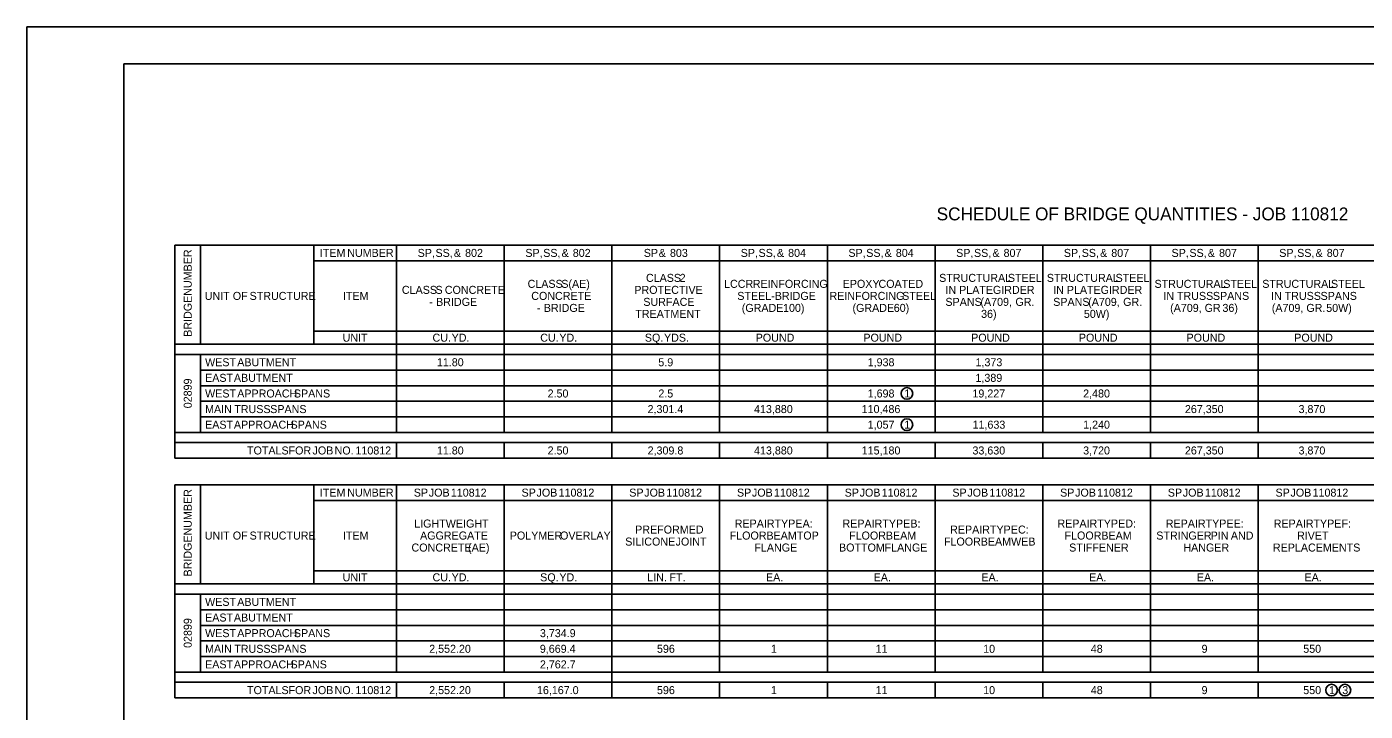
# Model space of a CAD drawing. Extents: x 188 to 14744886, y 129 to 1829278.
# Drawn here: x 187.88 to 208.75, y 139.85 to 150.51 of the extents above; entities that cross this region are included whole.
import ezdxf

# ---------------------------------------------------------------- set-up
doc = ezdxf.new("R2010")
doc.units = 0
for name, color, linetype in [('B_Dimensions', 7, 'Continuous'), ('B_Text', 7, 'Continuous'), ('B_Title Text', 7, 'Continuous'), ('R_Border', 7, 'Continuous'), ('R_No Plot', 7, 'Continuous')]:
    doc.layers.add(name, color=color, linetype=linetype)

msp = doc.modelspace()

# ---------------------------------------------------------------- linework, layer by layer
at = {"layer": 'B_Dimensions'}
msp.add_line((190.192, 147.111), (190.192, 147.111), dxfattribs=at)
for centre in [(201.604, 144.799), (201.604, 144.312), (208.225, 140.175), (208.433, 140.175)]:
    msp.add_circle(centre, 0.0908, dxfattribs=at)
at = {"layer": 'B_Text'}
for p, q in [((190.192, 147.111), (220.514, 147.111)), ((190.192, 143.789), (190.192, 147.111)), ((190.593, 145.565), (190.593, 147.111)), ((192.357, 145.565), (192.357, 147.111)), ((192.357, 145.565), (192.357, 147.111)), ((193.647, 144.19), (193.647, 147.111)), ((195.326, 144.19), (195.326, 147.111)), ((197.006, 144.19), (197.006, 147.111)), ((198.685, 144.19), (198.685, 147.111)), ((200.364, 144.19), (200.364, 147.111)), ((202.043, 144.19), (202.043, 147.111)), ((203.722, 144.19), (203.722, 147.111)), ((205.402, 144.19), (205.402, 147.111)), ((207.081, 144.19), (207.081, 147.111)), ((192.357, 146.867), (220.514, 146.867)), ((192.357, 145.772), (220.514, 145.772)), ((190.192, 145.565), (220.514, 145.565)), ((190.192, 145.407), (220.514, 145.407)), ((190.593, 144.19), (190.593, 145.407)), ((190.593, 145.164), (220.514, 145.164)), ((190.593, 144.92), (220.514, 144.92)), ((190.593, 144.677), (220.514, 144.677)), ((190.593, 144.434), (220.514, 144.434)), ((190.192, 144.19), (220.514, 144.19)), ((190.192, 144.032), (220.514, 144.032)), ((193.647, 143.789), (193.647, 144.032)), ((195.326, 143.789), (195.326, 144.032)), ((197.006, 143.789), (197.006, 144.032)), ((198.685, 143.789), (198.685, 144.032)), ((200.364, 143.789), (200.364, 144.032)), ((202.043, 143.789), (202.043, 144.032)), ((203.722, 143.789), (203.722, 144.032)), ((205.402, 143.789), (205.402, 144.032)), ((207.081, 143.789), (207.081, 144.032)), ((190.192, 143.789), (220.514, 143.789)), ((190.192, 143.375), (220.514, 143.375)), ((190.192, 140.053), (190.192, 143.375)), ((190.593, 141.83), (190.593, 143.375)), ((192.357, 141.83), (192.357, 143.375)), ((192.357, 141.83), (192.357, 143.375)), ((193.647, 140.455), (193.647, 143.375)), ((195.326, 140.455), (195.326, 143.375)), ((197.006, 140.053), (197.006, 143.375)), ((198.685, 140.455), (198.685, 143.375)), ((200.364, 140.455), (200.364, 143.375)), ((202.043, 140.455), (202.043, 143.375)), ((203.722, 140.455), (203.722, 143.375)), ((205.402, 140.455), (205.402, 143.375)), ((207.081, 140.455), (207.081, 143.375)), ((192.357, 143.132), (220.514, 143.132)), ((192.357, 142.037), (220.514, 142.037)), ((190.192, 141.83), (220.514, 141.83)), ((190.192, 141.672), (220.514, 141.672)), ((190.593, 140.455), (190.593, 141.672)), ((190.593, 141.428), (220.514, 141.428)), ((190.593, 141.185), (220.514, 141.185)), ((190.593, 140.942), (220.514, 140.942)), ((197.006, 140.698), (197.006, 140.942)), ((198.685, 140.698), (198.685, 140.942)), ((190.593, 140.698), (220.514, 140.698)), ((197.006, 140.698), (198.685, 140.698)), ((198.685, 140.698), (220.514, 140.698)), ((190.192, 140.455), (220.514, 140.455)), ((197.006, 140.297), (197.006, 140.455)), ((190.192, 140.297), (220.514, 140.297)), ((193.647, 140.053), (193.647, 140.297)), ((195.326, 140.053), (195.326, 140.297)), ((198.685, 140.053), (198.685, 140.297)), ((200.364, 140.053), (200.364, 140.297)), ((202.043, 140.053), (202.043, 140.297)), ((203.722, 140.053), (203.722, 140.297)), ((205.402, 140.053), (205.402, 140.297)), ((207.081, 140.053), (207.081, 140.297)), ((190.192, 140.053), (193.647, 140.053)), ((190.192, 140.053), (192.357, 140.053)), ((192.357, 140.053), (220.514, 140.053)), ((197.006, 140.053), (218.835, 140.053))]:
    msp.add_line(p, q, dxfattribs=at)
at = {"layer": 'R_Border'}
for p, q in [((189.399, 149.937), (221.306, 149.937)), ((189.399, 129.091), (189.399, 149.937))]:
    msp.add_line(p, q, dxfattribs=at)
at = {"layer": 'R_No Plot'}
msp.add_lwpolyline([(187.883, 150.514), (221.883, 150.514), (221.883, 128.514), (187.883, 128.514)], close=True, dxfattribs=at)

# ---------------------------------------------------------------- texts
at = {"layer": 'B_Text'}
for s, p in [(' NUMBER', (190.455, 146.275)), ('BRIDGE', (190.455, 145.682)), ('02899', (190.455, 144.568)), (' NUMBER', (190.455, 142.539)), ('BRIDGE', (190.455, 141.946)), ('02899', (190.455, 140.833))]:
    msp.add_text(s, height=0.1248, rotation=90, dxfattribs=at).set_placement(p)
for s, height, p in [('ITEM', 0.1248, (192.452, 146.927)), (' NUMBER', 0.1248, (192.833, 146.927)), ('SP,', 0.1248, (193.977, 146.927)), (' SS,', 0.1248, (194.209, 146.927)), (' &', 0.1248, (194.495, 146.927)), (' 802', 0.1248, (194.67, 146.927)), ('SP,', 0.1248, (195.656, 146.927)), (' SS,', 0.1248, (195.888, 146.927)), (' &', 0.1248, (196.175, 146.927)), (' 802', 0.1248, (196.349, 146.927)), ('SP', 0.1248, (197.502, 146.927)), (' &', 0.1248, (197.689, 146.927)), (' 803', 0.1248, (197.864, 146.927)), ('SP,', 0.1248, (199.013, 146.927)), (' SS,', 0.1248, (199.245, 146.927)), (' &', 0.1248, (199.531, 146.927)), (' 804', 0.1248, (199.706, 146.927)), ('SP,', 0.1248, (200.692, 146.927)), (' SS,', 0.1248, (200.924, 146.927)), (' &', 0.1248, (201.21, 146.927)), (' 804', 0.1248, (201.385, 146.927)), ('SP,', 0.1248, (202.372, 146.927)), (' SS,', 0.1248, (202.604, 146.927)), (' &', 0.1248, (202.891, 146.927)), (' 807', 0.1248, (203.065, 146.927)), ('SP,', 0.1248, (204.051, 146.927)), (' SS,', 0.1248, (204.283, 146.927)), (' &', 0.1248, (204.57, 146.927)), (' 807', 0.1248, (204.744, 146.927)), ('SP,', 0.1248, (205.73, 146.927)), (' SS,', 0.1248, (205.962, 146.927)), (' &', 0.1248, (206.249, 146.927)), (' 807', 0.1248, (206.424, 146.927)), ('SP,', 0.1248, (207.409, 146.927)), (' SS,', 0.1248, (207.642, 146.927)), (' &', 0.1248, (207.928, 146.927)), (' 807', 0.1248, (208.103, 146.927)), ('CLASS', 0.1248, (195.691, 146.445)), (' S(AE)', 0.1248, (196.17, 146.445)), ('CLASS', 0.1248, (197.536, 146.538)), (' 2', 0.1248, (198.015, 146.538)), ('LCCR', 0.1248, (198.754, 146.445)), (' REINFORCING', 0.1248, (199.155, 146.445)), ('EPOXY', 0.1248, (200.603, 146.445)), (' COATED', 0.1248, (201.115, 146.445)), ('STRUCTURAL', 0.1248, (202.107, 146.538)), (' STEEL', 0.1248, (203.132, 146.538)), ('STRUCTURAL', 0.1248, (203.786, 146.538)), (' STEEL', 0.1248, (204.811, 146.538)), ('STRUCTURAL', 0.1248, (205.465, 146.445)), (' STEEL', 0.1248, (206.49, 146.445)), ('STRUCTURAL', 0.1248, (207.144, 146.445)), (' STEEL', 0.1248, (208.169, 146.445)), ('UNIT', 0.1248, (190.658, 146.257)), (' OF', 0.1248, (191.049, 146.257)), (' STRUCTURE', 0.1248, (191.311, 146.257)), ('ITEM', 0.1248, (192.812, 146.257)), ('CLASS', 0.1248, (193.731, 146.351)), (' S', 0.1248, (194.209, 146.351)), (' BRIDGE', 0.1248, (194.218, 146.164)), (' CONCRETE', 0.1248, (194.354, 146.351)), ('CONCRETE', 0.1248, (195.748, 146.257)), ('PROTECTIVE', 0.1248, (197.355, 146.351)), ('SURFACE', 0.1248, (197.495, 146.164)), ('STEEL-BRIDGE', 0.1248, (198.96, 146.257)), ('REINFORCING', 0.1248, (200.397, 146.257)), (' STEEL', 0.1248, (201.484, 146.257)), ('SPANS', 0.1248, (202.205, 146.164)), ('IN', 0.1248, (202.206, 146.351)), (' PLATE', 0.1248, (202.372, 146.351)), (' (A709,', 0.1248, (202.704, 146.164)), (' GIRDER', 0.1248, (202.899, 146.351)), (' GR.', 0.1248, (203.25, 146.164)), ('SPANS', 0.1248, (203.885, 146.164)), ('IN', 0.1248, (203.885, 146.351)), (' PLATE', 0.1248, (204.051, 146.351)), (' (A709,', 0.1248, (204.384, 146.164)), (' GIRDER', 0.1248, (204.578, 146.351)), (' GR.', 0.1248, (204.929, 146.164)), ('IN', 0.1248, (205.602, 146.257)), (' TRUSS', 0.1248, (205.768, 146.257)), (' SPANS', 0.1248, (206.328, 146.257)), ('IN', 0.1248, (207.281, 146.257)), (' TRUSS', 0.1248, (207.447, 146.257)), (' SPANS', 0.1248, (208.007, 146.257)), (' -', 0.1248, (194.109, 146.164)), (' -', 0.1248, (195.788, 146.07)), (' BRIDGE', 0.1248, (195.897, 146.07)), ('TREATMENT', 0.1248, (197.37, 145.977)), ('(GRADE', 0.1248, (199.03, 146.07)), (' 100)', 0.1248, (199.627, 146.07)), ('(GRADE', 0.1248, (200.756, 146.07)), (' 60)', 0.1248, (201.353, 146.07)), ('36)', 0.1248, (202.761, 145.977)), ('50W)', 0.1248, (204.363, 145.977)), ('(A709,', 0.1248, (205.708, 146.07)), (' GR', 0.1248, (206.199, 146.07)), (' 36)', 0.1248, (206.477, 146.07)), ('(A709,', 0.1248, (207.293, 146.07)), (' GR.', 0.1248, (207.785, 146.07)), (' 50W)', 0.1248, (208.095, 146.07)), ('UNIT', 0.1248, (192.807, 145.606)), ('CU.', 0.1248, (194.209, 145.606)), (' YD.', 0.1248, (194.46, 145.606)), ('CU.', 0.1248, (195.888, 145.606)), (' YD.', 0.1248, (196.139, 145.606)), ('SQ.', 0.1248, (197.519, 145.606)), (' YDS.', 0.1248, (197.771, 145.606)), ('POUND', 0.1248, (199.247, 145.606)), ('POUND', 0.1248, (200.926, 145.606)), ('POUND', 0.1248, (202.606, 145.606)), ('POUND', 0.1248, (204.285, 145.606)), ('POUND', 0.1248, (205.964, 145.606)), ('POUND', 0.1248, (207.643, 145.606)), (' WEST', 0.1248, (190.617, 145.223)), (' ABUTMENT', 0.1248, (191.118, 145.223)), ('11.80', 0.1248, (194.277, 145.223)), ('5.9', 0.1248, (197.729, 145.223)), ('1,938', 0.1248, (200.993, 145.223)), ('1,373', 0.1248, (202.674, 145.223)), (' EAST', 0.1248, (190.617, 144.98)), (' ABUTMENT', 0.1248, (191.066, 144.98)), ('1,389', 0.1248, (202.673, 144.98)), (' WEST', 0.1248, (190.617, 144.736)), (' APPROACH', 0.1248, (191.118, 144.736)), (' SPANS', 0.1248, (192.001, 144.736)), ('2.50', 0.1248, (196.003, 144.736)), ('2.5', 0.1248, (197.73, 144.736)), ('1,698', 0.1248, (200.993, 144.736)), ('1', 0.125, (201.564, 144.736)), ('19,227', 0.1248, (202.626, 144.736)), ('2,480', 0.1248, (204.352, 144.736)), (' MAIN', 0.1248, (190.617, 144.493)), (' TRUSS', 0.1248, (191.072, 144.493)), (' SPANS', 0.1248, (191.632, 144.493)), ('2,301.4', 0.1248, (197.561, 144.493)), ('413,880', 0.1248, (199.221, 144.493)), ('110,486', 0.1248, (200.899, 144.493)), ('267,350', 0.1248, (205.938, 144.493)), ('3,870', 0.1248, (207.71, 144.493)), (' EAST', 0.1248, (190.617, 144.25)), (' APPROACH', 0.1248, (191.066, 144.25)), (' SPANS', 0.1248, (191.949, 144.25)), ('1,057', 0.1248, (200.993, 144.25)), ('1', 0.125, (201.564, 144.25)), ('11,633', 0.1248, (202.628, 144.25)), ('1,240', 0.1248, (204.352, 144.25)), ('TOTALS', 0.1248, (191.317, 143.848)), (' FOR', 0.1248, (191.918, 143.848)), (' JOB', 0.1248, (192.292, 143.848)), (' NO.', 0.1248, (192.636, 143.848)), (' 110812', 0.1248, (192.961, 143.848)), ('11.80', 0.1248, (194.277, 143.848)), ('2.50', 0.1248, (196.003, 143.848)), ('2,309.8', 0.1248, (197.562, 143.848)), ('413,880', 0.1248, (199.221, 143.848)), ('115,180', 0.1248, (200.9, 143.848)), ('33,630', 0.1248, (202.626, 143.848)), ('3,720', 0.1248, (204.352, 143.848)), ('267,350', 0.1248, (205.938, 143.848)), ('3,870', 0.1248, (207.71, 143.848)), ('ITEM', 0.1248, (192.452, 143.191)), (' NUMBER', 0.1248, (192.833, 143.191)), ('SP', 0.1248, (193.917, 143.191)), (' JOB', 0.1248, (194.105, 143.191)), (' 110812', 0.1248, (194.448, 143.191)), ('SP', 0.1248, (195.597, 143.191)), (' JOB', 0.1248, (195.784, 143.191)), (' 110812', 0.1248, (196.128, 143.191)), ('SP', 0.1248, (197.276, 143.191)), (' JOB', 0.1248, (197.463, 143.191)), (' 110812', 0.1248, (197.807, 143.191)), ('SP', 0.1248, (198.955, 143.191)), (' JOB', 0.1248, (199.142, 143.191)), (' 110812', 0.1248, (199.486, 143.191)), ('SP', 0.1248, (200.634, 143.191)), (' JOB', 0.1248, (200.821, 143.191)), (' 110812', 0.1248, (201.165, 143.191)), ('SP', 0.1248, (202.313, 143.191)), (' JOB', 0.1248, (202.5, 143.191)), (' 110812', 0.1248, (202.844, 143.191)), ('SP', 0.1248, (203.993, 143.191)), (' JOB', 0.1248, (204.18, 143.191)), (' 110812', 0.1248, (204.523, 143.191)), ('SP', 0.1248, (205.672, 143.191)), (' JOB', 0.1248, (205.859, 143.191)), (' 110812', 0.1248, (206.203, 143.191)), ('SP', 0.1248, (207.351, 143.191)), (' JOB', 0.1248, (207.538, 143.191)), (' 110812', 0.1248, (207.882, 143.191)), ('LIGHTWEIGHT', 0.1248, (193.924, 142.709)), ('PREFORMED', 0.1248, (197.368, 142.615)), ('REPAIR', 0.1248, (198.92, 142.709)), (' TYPE', 0.1248, (199.494, 142.709)), (' A:', 0.1248, (199.932, 142.709)), ('REPAIR', 0.1248, (200.6, 142.709)), (' TYPE', 0.1248, (201.174, 142.709)), (' B:', 0.1248, (201.612, 142.709)), ('REPAIR', 0.1248, (202.278, 142.615)), (' TYPE', 0.1248, (202.852, 142.615)), (' C:', 0.1248, (203.29, 142.615)), ('REPAIR', 0.1248, (203.951, 142.709)), (' TYPE', 0.1248, (204.525, 142.709)), (' D:', 0.1248, (204.963, 142.709)), ('REPAIR', 0.1248, (205.64, 142.709)), (' TYPE', 0.1248, (206.214, 142.709)), (' E:', 0.1248, (206.652, 142.709)), ('REPAIR', 0.1248, (207.323, 142.709)), (' TYPE', 0.1248, (207.896, 142.709)), (' F:', 0.1248, (208.334, 142.709)), ('UNIT', 0.1248, (190.658, 142.522)), (' OF', 0.1248, (191.049, 142.522)), (' STRUCTURE', 0.1248, (191.311, 142.522)), ('ITEM', 0.1248, (192.812, 142.522)), ('AGGREGATE', 0.1248, (194.015, 142.522)), ('POLYMER', 0.1248, (195.413, 142.522)), (' OVERLAY', 0.1248, (196.151, 142.522)), ('SILICONE', 0.1248, (197.213, 142.428)), (' JOINT', 0.1248, (197.952, 142.428)), ('FLOOR', 0.1248, (198.841, 142.522)), (' BEAM', 0.1248, (199.368, 142.522)), (' TOP', 0.1248, (199.841, 142.522)), ('FLOOR', 0.1248, (200.703, 142.522)), (' BEAM', 0.1248, (201.23, 142.522)), ('FLOOR', 0.1248, (202.182, 142.428)), (' BEAM', 0.1248, (202.709, 142.428)), (' WEB', 0.1248, (203.182, 142.428)), ('FLOOR', 0.1248, (204.062, 142.522)), (' BEAM', 0.1248, (204.589, 142.522)), ('STRINGER', 0.1248, (205.492, 142.522)), (' PIN', 0.1248, (206.293, 142.522)), (' AND', 0.1248, (206.608, 142.522)), ('RIVET', 0.1248, (207.686, 142.522)), ('CONCRETE', 0.1248, (193.881, 142.335)), (' (AE)', 0.1248, (194.717, 142.335)), ('FLANGE', 0.1248, (199.226, 142.335)), ('BOTTOM', 0.1248, (200.546, 142.335)), (' FLANGE', 0.1248, (201.21, 142.335)), ('STIFFENER', 0.1248, (204.134, 142.335)), ('HANGER', 0.1248, (205.914, 142.335)), ('REPLACEMENTS', 0.1248, (207.31, 142.335)), ('UNIT', 0.1248, (192.807, 141.871)), ('CU.', 0.1248, (194.209, 141.871)), (' YD.', 0.1248, (194.46, 141.871)), ('SQ.', 0.1248, (195.887, 141.871)), (' YD.', 0.1248, (196.14, 141.871)), ('LIN.', 0.1248, (197.556, 141.871)), (' FT.', 0.1248, (197.856, 141.871)), ('EA.', 0.1248, (199.407, 141.871)), ('EA.', 0.1248, (201.086, 141.871)), ('EA.', 0.1248, (202.765, 141.871)), ('EA.', 0.1248, (204.444, 141.871)), ('EA.', 0.1248, (206.124, 141.871)), ('EA.', 0.1248, (207.803, 141.871)), (' WEST', 0.1248, (190.617, 141.488)), (' ABUTMENT', 0.1248, (191.118, 141.488)), (' EAST', 0.1248, (190.617, 141.244)), (' ABUTMENT', 0.1248, (191.066, 141.244)), (' WEST', 0.1248, (190.617, 141.001)), (' APPROACH', 0.1248, (191.118, 141.001)), (' SPANS', 0.1248, (192.001, 141.001)), ('3,734.9', 0.1248, (195.883, 141.001)), (' MAIN', 0.1248, (190.617, 140.757)), (' TRUSS', 0.1248, (191.072, 140.757)), (' SPANS', 0.1248, (191.632, 140.757)), ('2,552.20', 0.1248, (194.157, 140.757)), ('9,669.4', 0.1248, (195.882, 140.757)), ('596', 0.1248, (197.708, 140.757)), ('1', 0.125, (199.485, 140.757)), ('11', 0.1248, (201.117, 140.757)), ('10', 0.1248, (202.793, 140.757)), ('48', 0.1248, (204.471, 140.757)), ('9', 0.125, (206.198, 140.757)), ('550', 0.1248, (207.783, 140.757)), (' EAST', 0.1248, (190.617, 140.514)), (' APPROACH', 0.1248, (191.066, 140.514)), (' SPANS', 0.1248, (191.949, 140.514)), ('2,762.7', 0.1248, (195.883, 140.514)), ('TOTALS', 0.1248, (191.317, 140.113)), (' FOR', 0.1248, (191.918, 140.113)), (' JOB', 0.1248, (192.292, 140.113)), (' NO.', 0.1248, (192.636, 140.113)), (' 110812', 0.1248, (192.961, 140.113)), ('2,552.20', 0.1248, (194.157, 140.113)), ('16,167.0', 0.1248, (195.837, 140.113)), ('596', 0.1248, (197.708, 140.113)), ('1', 0.125, (199.485, 140.113)), ('11', 0.1248, (201.117, 140.113)), ('10', 0.1248, (202.793, 140.113)), ('48', 0.1248, (204.471, 140.113)), ('9', 0.125, (206.198, 140.113)), ('550', 0.1248, (207.783, 140.113)), ('1', 0.125, (208.185, 140.113)), ('3', 0.125, (208.391, 140.113))]:
    msp.add_text(s, height=height, dxfattribs=at).set_placement(p)
at = {"layer": 'B_Title Text'}
msp.add_text('SCHEDULE OF BRIDGE QUANTITIES - JOB 110812', height=0.2004, dxfattribs=at).set_placement((202.068, 147.497))

doc.saveas('drawing.dxf')
